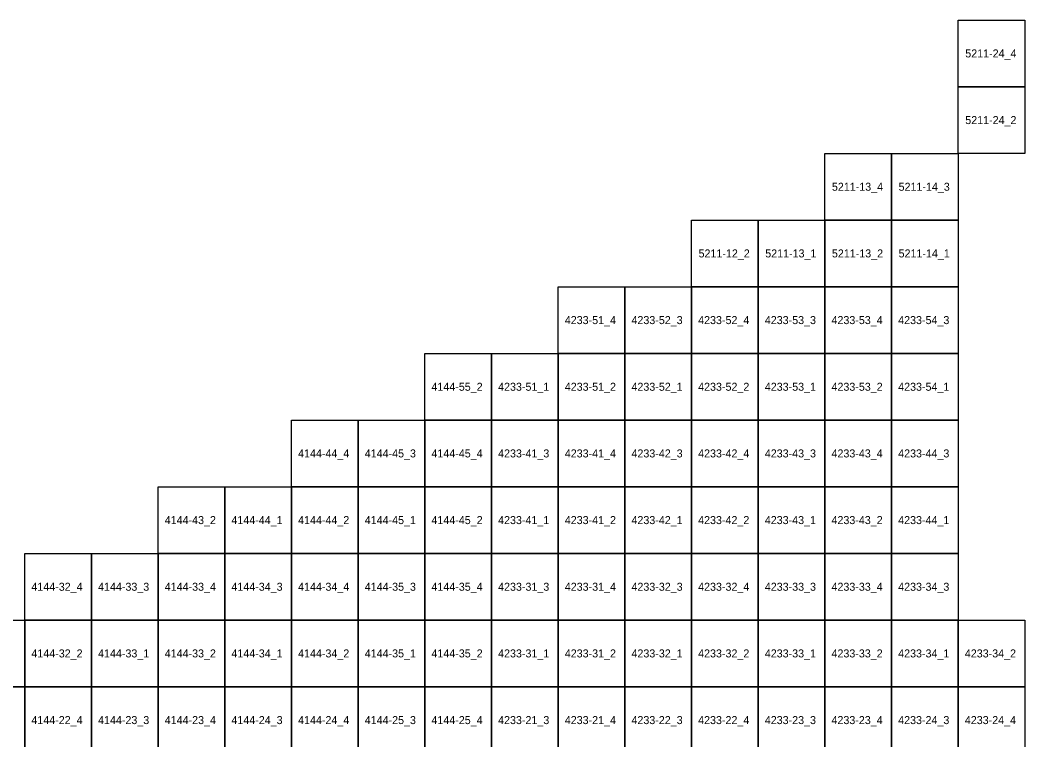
# Model space of a CAD drawing. Extents: x 312500 to 765000, y 172500 to 440000.
# Drawn here: x 382325 to 420000, y 383007 to 410000 of the extents above; entities that cross this region are included whole.
import ezdxf

# ---------------------------------------------------------------- set-up
doc = ezdxf.new("R2010")
doc.units = 0
doc.layers.add('Topo5_ramis_TKS2025', color=7, linetype='Continuous')
doc.layers.add('Topo5_ramis_TKS2025_Nr', color=7, linetype='Continuous')

msp = doc.modelspace()

# ---------------------------------------------------------------- linework, layer by layer
at = {"layer": 'Topo5_ramis_TKS2025'}
for points in [[(417500, 407500), (417500, 410000), (420000, 410000), (420000, 407500), (417500, 407500)], [(417500, 405000), (417500, 407500), (420000, 407500), (420000, 405000), (417500, 405000)], [(412500, 402500), (412500, 405000), (415000, 405000), (415000, 402500), (412500, 402500)], [(415000, 402500), (415000, 405000), (417500, 405000), (417500, 402500), (415000, 402500)], [(407500, 400000), (407500, 402500), (410000, 402500), (410000, 400000), (407500, 400000)], [(410000, 400000), (410000, 402500), (412500, 402500), (412500, 400000), (410000, 400000)], [(412500, 400000), (412500, 402500), (415000, 402500), (415000, 400000), (412500, 400000)], [(415000, 400000), (415000, 402500), (417500, 402500), (417500, 400000), (415000, 400000)], [(402500, 397500), (402500, 400000), (405000, 400000), (405000, 397500), (402500, 397500)], [(405000, 397500), (405000, 400000), (407500, 400000), (407500, 397500), (405000, 397500)], [(407500, 397500), (407500, 400000), (410000, 400000), (410000, 397500), (407500, 397500)], [(410000, 397500), (410000, 400000), (412500, 400000), (412500, 397500), (410000, 397500)], [(412500, 397500), (412500, 400000), (415000, 400000), (415000, 397500), (412500, 397500)], [(415000, 397500), (415000, 400000), (417500, 400000), (417500, 397500), (415000, 397500)], [(397500, 395000), (397500, 397500), (400000, 397500), (400000, 395000), (397500, 395000)], [(400000, 395000), (400000, 397500), (402500, 397500), (402500, 395000), (400000, 395000)], [(402500, 395000), (402500, 397500), (405000, 397500), (405000, 395000), (402500, 395000)], [(405000, 395000), (405000, 397500), (407500, 397500), (407500, 395000), (405000, 395000)], [(407500, 395000), (407500, 397500), (410000, 397500), (410000, 395000), (407500, 395000)], [(410000, 395000), (410000, 397500), (412500, 397500), (412500, 395000), (410000, 395000)], [(412500, 395000), (412500, 397500), (415000, 397500), (415000, 395000), (412500, 395000)], [(415000, 395000), (415000, 397500), (417500, 397500), (417500, 395000), (415000, 395000)], [(392500, 392500), (392500, 395000), (395000, 395000), (395000, 392500), (392500, 392500)], [(395000, 392500), (395000, 395000), (397500, 395000), (397500, 392500), (395000, 392500)], [(397500, 392500), (397500, 395000), (400000, 395000), (400000, 392500), (397500, 392500)], [(400000, 392500), (400000, 395000), (402500, 395000), (402500, 392500), (400000, 392500)], [(402500, 392500), (402500, 395000), (405000, 395000), (405000, 392500), (402500, 392500)], [(405000, 392500), (405000, 395000), (407500, 395000), (407500, 392500), (405000, 392500)], [(407500, 392500), (407500, 395000), (410000, 395000), (410000, 392500), (407500, 392500)], [(410000, 392500), (410000, 395000), (412500, 395000), (412500, 392500), (410000, 392500)], [(412500, 392500), (412500, 395000), (415000, 395000), (415000, 392500), (412500, 392500)], [(415000, 392500), (415000, 395000), (417500, 395000), (417500, 392500), (415000, 392500)], [(387500, 390000), (387500, 392500), (390000, 392500), (390000, 390000), (387500, 390000)], [(390000, 390000), (390000, 392500), (392500, 392500), (392500, 390000), (390000, 390000)], [(392500, 390000), (392500, 392500), (395000, 392500), (395000, 390000), (392500, 390000)], [(395000, 390000), (395000, 392500), (397500, 392500), (397500, 390000), (395000, 390000)], [(397500, 390000), (397500, 392500), (400000, 392500), (400000, 390000), (397500, 390000)], [(400000, 390000), (400000, 392500), (402500, 392500), (402500, 390000), (400000, 390000)], [(402500, 390000), (402500, 392500), (405000, 392500), (405000, 390000), (402500, 390000)], [(405000, 390000), (405000, 392500), (407500, 392500), (407500, 390000), (405000, 390000)], [(407500, 390000), (407500, 392500), (410000, 392500), (410000, 390000), (407500, 390000)], [(410000, 390000), (410000, 392500), (412500, 392500), (412500, 390000), (410000, 390000)], [(412500, 390000), (412500, 392500), (415000, 392500), (415000, 390000), (412500, 390000)], [(415000, 390000), (415000, 392500), (417500, 392500), (417500, 390000), (415000, 390000)], [(382500, 387500), (382500, 390000), (385000, 390000), (385000, 387500), (382500, 387500)], [(385000, 387500), (385000, 390000), (387500, 390000), (387500, 387500), (385000, 387500)], [(387500, 387500), (387500, 390000), (390000, 390000), (390000, 387500), (387500, 387500)], [(390000, 387500), (390000, 390000), (392500, 390000), (392500, 387500), (390000, 387500)], [(392500, 387500), (392500, 390000), (395000, 390000), (395000, 387500), (392500, 387500)], [(395000, 387500), (395000, 390000), (397500, 390000), (397500, 387500), (395000, 387500)], [(397500, 387500), (397500, 390000), (400000, 390000), (400000, 387500), (397500, 387500)], [(400000, 387500), (400000, 390000), (402500, 390000), (402500, 387500), (400000, 387500)], [(402500, 387500), (402500, 390000), (405000, 390000), (405000, 387500), (402500, 387500)], [(405000, 387500), (405000, 390000), (407500, 390000), (407500, 387500), (405000, 387500)], [(407500, 387500), (407500, 390000), (410000, 390000), (410000, 387500), (407500, 387500)], [(410000, 387500), (410000, 390000), (412500, 390000), (412500, 387500), (410000, 387500)], [(412500, 387500), (412500, 390000), (415000, 390000), (415000, 387500), (412500, 387500)], [(415000, 387500), (415000, 390000), (417500, 390000), (417500, 387500), (415000, 387500)], [(380000, 385000), (380000, 387500), (382500, 387500), (382500, 385000), (380000, 385000)], [(382500, 385000), (382500, 387500), (385000, 387500), (385000, 385000), (382500, 385000)], [(385000, 385000), (385000, 387500), (387500, 387500), (387500, 385000), (385000, 385000)], [(387500, 385000), (387500, 387500), (390000, 387500), (390000, 385000), (387500, 385000)], [(390000, 385000), (390000, 387500), (392500, 387500), (392500, 385000), (390000, 385000)], [(392500, 385000), (392500, 387500), (395000, 387500), (395000, 385000), (392500, 385000)], [(395000, 385000), (395000, 387500), (397500, 387500), (397500, 385000), (395000, 385000)], [(397500, 385000), (397500, 387500), (400000, 387500), (400000, 385000), (397500, 385000)], [(400000, 385000), (400000, 387500), (402500, 387500), (402500, 385000), (400000, 385000)], [(402500, 385000), (402500, 387500), (405000, 387500), (405000, 385000), (402500, 385000)], [(405000, 385000), (405000, 387500), (407500, 387500), (407500, 385000), (405000, 385000)], [(407500, 385000), (407500, 387500), (410000, 387500), (410000, 385000), (407500, 385000)], [(410000, 385000), (410000, 387500), (412500, 387500), (412500, 385000), (410000, 385000)], [(412500, 385000), (412500, 387500), (415000, 387500), (415000, 385000), (412500, 385000)], [(415000, 385000), (415000, 387500), (417500, 387500), (417500, 385000), (415000, 385000)], [(417500, 385000), (417500, 387500), (420000, 387500), (420000, 385000), (417500, 385000)], [(380000, 382500), (380000, 385000), (382500, 385000), (382500, 382500), (380000, 382500)], [(382500, 382500), (382500, 385000), (385000, 385000), (385000, 382500), (382500, 382500)], [(385000, 382500), (385000, 385000), (387500, 385000), (387500, 382500), (385000, 382500)], [(387500, 382500), (387500, 385000), (390000, 385000), (390000, 382500), (387500, 382500)], [(390000, 382500), (390000, 385000), (392500, 385000), (392500, 382500), (390000, 382500)], [(392500, 382500), (392500, 385000), (395000, 385000), (395000, 382500), (392500, 382500)], [(395000, 382500), (395000, 385000), (397500, 385000), (397500, 382500), (395000, 382500)], [(397500, 382500), (397500, 385000), (400000, 385000), (400000, 382500), (397500, 382500)], [(400000, 382500), (400000, 385000), (402500, 385000), (402500, 382500), (400000, 382500)], [(402500, 382500), (402500, 385000), (405000, 385000), (405000, 382500), (402500, 382500)], [(405000, 382500), (405000, 385000), (407500, 385000), (407500, 382500), (405000, 382500)], [(407500, 382500), (407500, 385000), (410000, 385000), (410000, 382500), (407500, 382500)], [(410000, 382500), (410000, 385000), (412500, 385000), (412500, 382500), (410000, 382500)], [(412500, 382500), (412500, 385000), (415000, 385000), (415000, 382500), (412500, 382500)], [(415000, 382500), (415000, 385000), (417500, 385000), (417500, 382500), (415000, 382500)], [(417500, 382500), (417500, 385000), (420000, 385000), (420000, 382500), (417500, 382500)]]:
    msp.add_lwpolyline(points, dxfattribs=at)

# ---------------------------------------------------------------- texts
at = {"layer": 'Topo5_ramis_TKS2025_Nr'}
for s, p in [('5211-24_4', (417764, 408600)), ('5211-24_2', (417764, 406100)), ('5211-13_4', (412764, 403600)), ('5211-14_3', (415264, 403600)), ('5211-12_2', (407764, 401100)), ('5211-13_1', (410264, 401100)), ('5211-13_2', (412764, 401100)), ('5211-14_1', (415264, 401100)), ('4233-51_4', (402748, 398600)), ('4233-52_3', (405248, 398600)), ('4233-52_4', (407748, 398600)), ('4233-53_3', (410248, 398600)), ('4233-53_4', (412748, 398600)), ('4233-54_3', (415248, 398600)), ('4144-55_2', (397748, 396100)), ('4233-51_1', (400248, 396100)), ('4233-51_2', (402748, 396100)), ('4233-52_1', (405248, 396100)), ('4233-52_2', (407748, 396100)), ('4233-53_1', (410248, 396100)), ('4233-53_2', (412748, 396100)), ('4233-54_1', (415248, 396100)), ('4144-44_4', (392748, 393600)), ('4144-45_3', (395248, 393600)), ('4144-45_4', (397748, 393600)), ('4233-41_3', (400248, 393600)), ('4233-41_4', (402748, 393600)), ('4233-42_3', (405248, 393600)), ('4233-42_4', (407748, 393600)), ('4233-43_3', (410248, 393600)), ('4233-43_4', (412748, 393600)), ('4233-44_3', (415248, 393600)), ('4144-43_2', (387748, 391100)), ('4144-44_1', (390248, 391100)), ('4144-44_2', (392748, 391100)), ('4144-45_1', (395248, 391100)), ('4144-45_2', (397748, 391100)), ('4233-41_1', (400248, 391100)), ('4233-41_2', (402748, 391100)), ('4233-42_1', (405248, 391100)), ('4233-42_2', (407748, 391100)), ('4233-43_1', (410248, 391100)), ('4233-43_2', (412748, 391100)), ('4233-44_1', (415248, 391100)), ('4144-32_4', (382748, 388600)), ('4144-33_3', (385248, 388600)), ('4144-33_4', (387748, 388600)), ('4144-34_3', (390248, 388600)), ('4144-34_4', (392748, 388600)), ('4144-35_3', (395248, 388600)), ('4144-35_4', (397748, 388600)), ('4233-31_3', (400248, 388600)), ('4233-31_4', (402748, 388600)), ('4233-32_3', (405248, 388600)), ('4233-32_4', (407748, 388600)), ('4233-33_3', (410248, 388600)), ('4233-33_4', (412748, 388600)), ('4233-34_3', (415248, 388600)), ('4144-32_2', (382748, 386100)), ('4144-33_1', (385248, 386100)), ('4144-33_2', (387748, 386100)), ('4144-34_1', (390248, 386100)), ('4144-34_2', (392748, 386100)), ('4144-35_1', (395248, 386100)), ('4144-35_2', (397748, 386100)), ('4233-31_1', (400248, 386100)), ('4233-31_2', (402748, 386100)), ('4233-32_1', (405248, 386100)), ('4233-32_2', (407748, 386100)), ('4233-33_1', (410248, 386100)), ('4233-33_2', (412748, 386100)), ('4233-34_1', (415248, 386100)), ('4233-34_2', (417748, 386100)), ('4144-22_4', (382748, 383600)), ('4144-23_3', (385248, 383600)), ('4144-23_4', (387748, 383600)), ('4144-24_3', (390248, 383600)), ('4144-24_4', (392748, 383600)), ('4144-25_3', (395248, 383600)), ('4144-25_4', (397748, 383600)), ('4233-21_3', (400248, 383600)), ('4233-21_4', (402748, 383600)), ('4233-22_3', (405248, 383600)), ('4233-22_4', (407748, 383600)), ('4233-23_3', (410248, 383600)), ('4233-23_4', (412748, 383600)), ('4233-24_3', (415248, 383600)), ('4233-24_4', (417748, 383600))]:
    msp.add_text(s, height=300, dxfattribs=at).set_placement(p)

doc.saveas('drawing.dxf')
